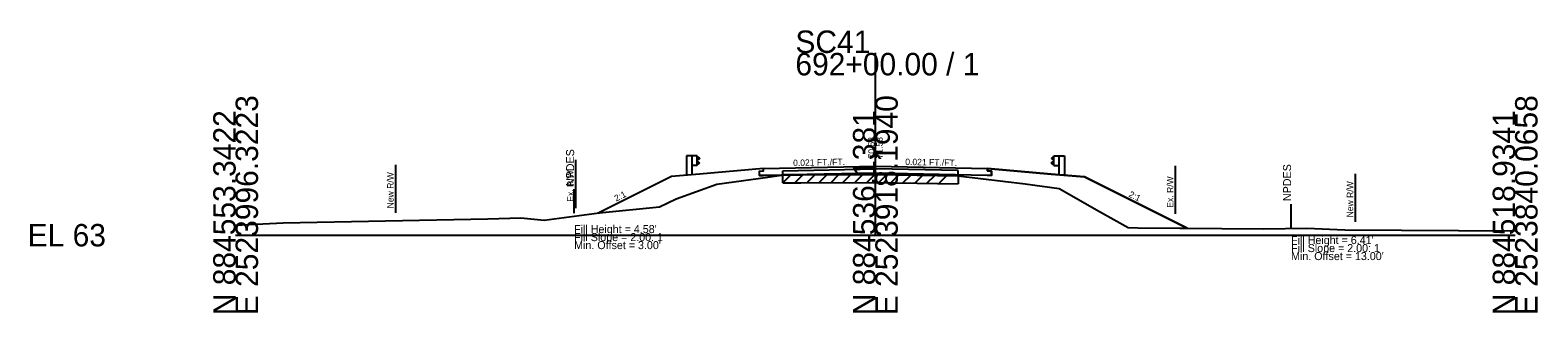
# Model space of a CAD drawing. Extents: x -26 to 183, y -10 to 24021.
# Drawn here: x -25.7 to 162.8, y 17990.3 to 18025.6 of the extents above; entities that cross this region are included whole.
import ezdxf

# ---------------------------------------------------------------- set-up
doc = ezdxf.new("R2010")
doc.units = 0
for name, color, linetype in [('RD_GPK_XS_Cell', 7, 'Continuous'), ('RD_XS_Base', 7, 'Continuous'), ('RD_XS_Buildup', 7, 'Continuous'), ('RD_XS_EarthShd', 7, 'Continuous'), ('RD_XS_EwShp', 7, 'Continuous'), ('RD_XS_ExGround', 7, 'Continuous'), ('RD_XS_ExPaveRet', 7, 'Continuous'), ('RD_XS_ExRW', 7, 'Continuous'), ('RD_XS_GR', 7, 'Continuous'), ('RD_XS_NewRW', 7, 'Continuous'), ('RD_XS_NPDES', 7, 'Continuous'), ('RD_XS_Pave', 7, 'Continuous'), ('RD_XS_TieSlope', 7, 'Continuous'), ('RD_XS_TX_Elev_EX', 7, 'Continuous'), ('RD_XS_TX_Elev_PR', 7, 'Continuous'), ('RD_XS_TX_Slope', 7, 'Continuous'), ('RD_XS_TX_Warning', 7, 'Continuous')]:
    doc.layers.add(name, color=color, linetype=linetype)

msp = doc.modelspace()

# ---------------------------------------------------------------- linework, layer by layer
at = {"layer": 'RD_GPK_XS_Cell'}
for p, q in [((80, 18000), (80, 18022.76)), ((0, 18000), (80, 18000)), ((80, 18000), (160, 18000))]:
    msp.add_line(p, q, dxfattribs=at)
at = {"layer": 'RD_XS_Base'}
for p in [(66.01, 18007.47), (93.99, 18007.47)]:
    msp.add_line(p, (80, 18007.76), dxfattribs=at)
at = {"layer": 'RD_XS_Buildup'}
for p, q in [((68.44, 18008.04), (80, 18008.28)), ((68.44, 18007.54), (68.44, 18008.04)), ((90.35, 18008.06), (80, 18008.28)), ((90.35, 18007.42), (90.35, 18008.06))]:
    msp.add_line(p, q, dxfattribs=at)
at = {"layer": 'RD_XS_EarthShd'}
for p, q in [((58, 18007.64), (54.5, 18007.35)), ((66, 18008.31), (58, 18007.64)), ((94, 18008.31), (102, 18007.64)), ((102, 18007.64), (106.17, 18007.29))]:
    msp.add_line(p, q, dxfattribs=at)
at = {"layer": 'RD_XS_EwShp'}
for points in [[(45.48, 18002.78), (52.99, 18003.54), (55.1, 18004.52), (60.19, 18006.36), (66.56, 18007.26), (68.26, 18007.51), (66.01, 18007.47), (65.5, 18007.46), (65.5, 18008.01), (66, 18008.02), (66, 18008.31), (58, 18007.64), (54.5, 18007.35), (45.33, 18002.76)], [(65.5, 18007.46), (65.5, 18008.01), (66, 18008.02), (66, 18008.31), (58, 18007.64), (54.5, 18007.35), (45.33, 18002.76), (45.48, 18002.78), (52.99, 18003.54), (55.1, 18004.52), (60.19, 18006.36), (66.56, 18007.26), (68.26, 18007.51), (66.01, 18007.47)], [(65.5, 18007.46), (65.5, 18008.01), (66, 18008.02), (66, 18008.31), (58, 18007.64), (54.5, 18007.35), (45.33, 18002.76), (45.48, 18002.78), (52.99, 18003.54), (55.1, 18004.52), (60.19, 18006.36), (66.56, 18007.26), (68.26, 18007.51), (66.01, 18007.47)], [(65.5, 18007.46), (65.5, 18008.01), (66, 18008.02), (66, 18008.31), (58, 18007.64), (54.5, 18007.35), (45.33, 18002.76), (45.48, 18002.78), (52.99, 18003.54), (55.1, 18004.52), (60.19, 18006.36), (66.56, 18007.26), (68.26, 18007.51), (66.01, 18007.47)], [(68.26, 18007.51), (69.36, 18007.54), (68.44, 18007.54)], [(68.44, 18007.54), (69.36, 18007.54), (68.26, 18007.51)], [(68.44, 18007.54), (69.36, 18007.54), (68.26, 18007.51)], [(68.44, 18007.54), (69.36, 18007.54), (68.26, 18007.51)], [(93.99, 18007.47), (80, 18007.76), (69.36, 18007.54), (70.66, 18007.53), (79.56, 18007.59), (80, 18007.58), (82.65, 18007.54), (90.35, 18007.42), (98.71, 18006.4), (103, 18005.83), (108.01, 18002.96), (111.62, 18000.94), (112.84, 18000.93), (118.98, 18000.89), (106.17, 18007.29), (102, 18007.64), (94, 18008.31), (94, 18008.02), (94.5, 18008.01), (94.5, 18007.46)], [(111.62, 18000.94), (112.84, 18000.93), (118.98, 18000.89), (106.17, 18007.29), (102, 18007.64), (94, 18008.31), (94, 18008.02), (94.5, 18008.01), (94.5, 18007.46), (93.99, 18007.47), (80, 18007.76), (69.36, 18007.54), (70.66, 18007.53), (79.56, 18007.59), (80, 18007.58), (82.65, 18007.54), (90.35, 18007.42), (98.71, 18006.4), (103, 18005.83), (108.01, 18002.96)], [(111.62, 18000.94), (112.84, 18000.93), (118.98, 18000.89), (106.17, 18007.29), (102, 18007.64), (94, 18008.31), (94, 18008.02), (94.5, 18008.01), (94.5, 18007.46), (93.99, 18007.47), (80, 18007.76), (69.36, 18007.54), (70.66, 18007.53), (79.56, 18007.59), (80, 18007.58), (82.65, 18007.54), (90.35, 18007.42), (98.71, 18006.4), (103, 18005.83), (108.01, 18002.96)], [(111.62, 18000.94), (112.84, 18000.93), (118.98, 18000.89), (106.17, 18007.29), (102, 18007.64), (94, 18008.31), (94, 18008.02), (94.5, 18008.01), (94.5, 18007.46), (93.99, 18007.47), (80, 18007.76), (69.36, 18007.54), (70.66, 18007.53), (79.56, 18007.59), (80, 18007.58), (82.65, 18007.54), (90.35, 18007.42), (98.71, 18006.4), (103, 18005.83), (108.01, 18002.96)]]:
    msp.add_lwpolyline(points, close=True, dxfattribs=at)
at = {"layer": 'RD_XS_ExGround'}
for p, q in [((60.19, 18006.36), (66.56, 18007.26)), ((66.56, 18007.26), (68.44, 18007.54)), ((68.44, 18007.54), (70.66, 18007.53)), ((70.66, 18007.53), (79.56, 18007.59)), ((79.56, 18007.59), (80, 18007.58)), ((80, 18007.58), (82.65, 18007.54)), ((82.65, 18007.54), (90.35, 18007.42)), ((90.35, 18007.42), (98.71, 18006.4)), ((55.1, 18004.52), (60.19, 18006.36)), ((98.71, 18006.4), (103, 18005.83)), ((103, 18005.83), (108.01, 18002.96)), ((45.48, 18002.78), (52.99, 18003.54)), ((52.99, 18003.54), (55.1, 18004.52)), ((0, 18001.27), (5.93, 18001.53)), ((5.93, 18001.53), (31.53, 18002.03)), ((31.53, 18002.03), (35.66, 18002.16)), ((35.66, 18002.16), (38.59, 18001.88)), ((38.59, 18001.88), (45.48, 18002.78)), ((108.01, 18002.96), (111.62, 18000.94)), ((111.62, 18000.94), (112.84, 18000.93)), ((112.84, 18000.93), (128.58, 18000.81)), ((128.58, 18000.81), (133.96, 18000.86)), ((133.96, 18000.86), (138.7, 18000.68)), ((138.7, 18000.68), (160, 18000.53))]:
    msp.add_line(p, q, dxfattribs=at)
at = {"layer": 'RD_XS_ExPaveRet'}
for p, q in [((68.44, 18006.54), (69.43, 18007.54)), ((68.44, 18006.54), (68.44, 18007.54)), ((69.94, 18006.53), (70.94, 18007.53)), ((71.44, 18006.54), (72.44, 18007.54)), ((72.94, 18006.54), (73.94, 18007.55)), ((74.44, 18006.55), (75.44, 18007.56)), ((75.94, 18006.56), (76.94, 18007.57)), ((77.44, 18006.57), (78.44, 18007.58)), ((78.94, 18006.58), (79.94, 18007.58)), ((80.44, 18006.57), (81.42, 18007.56)), ((81.94, 18006.55), (82.92, 18007.54)), ((83.44, 18006.53), (84.42, 18007.51)), ((84.94, 18006.51), (85.92, 18007.49)), ((86.44, 18006.48), (87.42, 18007.47)), ((87.94, 18006.46), (88.92, 18007.44)), ((90.35, 18007.42), (90.35, 18006.42)), ((68.44, 18006.54), (70.66, 18006.53)), ((70.66, 18006.53), (79.56, 18006.59)), ((79.56, 18006.59), (80, 18006.58)), ((80, 18006.58), (82.65, 18006.54)), ((82.65, 18006.54), (90.35, 18006.42))]:
    msp.add_line(p, q, dxfattribs=at)
at = {"layer": 'RD_XS_ExRW'}
for p, q in [((42.5, 18009.39), (42.5, 18003.39)), ((117.5, 18008.65), (117.5, 18002.65))]:
    msp.add_line(p, q, dxfattribs=at)
at = {"layer": 'RD_XS_GR'}
for p, q in [((56.4, 18009.89), (56.4, 18007.51)), ((57.06, 18009.89), (56.4, 18009.89)), ((57.06, 18009.89), (57.06, 18007.56)), ((57.73, 18009.89), (57.06, 18009.89)), ((57.73, 18008.72), (57.06, 18008.72)), ((57.73, 18008.72), (57.73, 18009.89)), ((57.73, 18009.82), (58, 18009.62)), ((58, 18009.57), (57.73, 18009.37)), ((58, 18009.05), (57.73, 18009.25)), ((57.73, 18008.8), (58, 18009)), ((58, 18009.62), (58, 18009.57)), ((58, 18009), (58, 18009.05)), ((102.3, 18009.81), (102.02, 18009.61)), ((102.02, 18009.61), (102.02, 18009.56)), ((102.02, 18009.56), (102.3, 18009.36)), ((102.02, 18009.04), (102.3, 18009.24)), ((102.02, 18008.99), (102.02, 18009.04)), ((102.3, 18008.79), (102.02, 18008.99)), ((102.3, 18009.89), (102.96, 18009.89)), ((102.3, 18008.72), (102.3, 18009.89)), ((102.3, 18008.72), (102.96, 18008.72)), ((102.96, 18009.89), (102.96, 18007.56)), ((102.96, 18009.89), (103.63, 18009.89)), ((103.63, 18009.89), (103.63, 18007.5)), ((102.96, 18007.56), (102.96, 18007.56))]:
    msp.add_line(p, q, dxfattribs=at)
at = {"layer": 'RD_XS_NewRW'}
for p, q in [((20, 18008.8), (20, 18002.8)), ((140, 18007.67), (140, 18001.67))]:
    msp.add_line(p, q, dxfattribs=at)
at = {"layer": 'RD_XS_NPDES'}
for p, q in [((42.33, 18002.76), (42.33, 18005.76)), ((131.98, 18000.89), (131.98, 18003.89))]:
    msp.add_line(p, q, dxfattribs=at)
at = {"layer": 'RD_XS_Pave'}
for p, q in [((65.5, 18008.01), (66, 18008.02)), ((65.5, 18007.46), (65.5, 18008.01)), ((65.5, 18007.46), (66.01, 18007.47)), ((66, 18008.31), (80, 18008.6)), ((66, 18008.02), (66, 18008.31)), ((80, 18008.6), (94, 18008.31)), ((94.5, 18007.46), (93.99, 18007.47)), ((94, 18008.02), (94, 18008.31)), ((94.5, 18008.01), (94, 18008.02)), ((94.5, 18007.46), (94.5, 18008.01))]:
    msp.add_line(p, q, dxfattribs=at)
at = {"layer": 'RD_XS_TieSlope'}
for p, q in [((54.5, 18007.35), (45.33, 18002.76)), ((106.17, 18007.29), (118.98, 18000.89))]:
    msp.add_line(p, q, dxfattribs=at)

# ---------------------------------------------------------------- texts
at = {"layer": 'RD_GPK_XS_Cell'}
for s, p in [('SC41', (70, 18022.76)), ('692+00.00 / 1', (70, 18019.96)), ('EL 63', (-26, 17998.6))]:
    msp.add_text(s, height=2.8, dxfattribs=at).set_placement(p)
for s, p in [('E 2523996.3223', (2.8, 17990)), ('E 2523918.1940', (82.8, 17990)), ('E 2523840.0658', (162.8, 17990)), ('N 884553.3422', (0, 17990)), ('N 884536.1381', (80, 17990)), ('N 884518.9341', (160, 17990))]:
    msp.add_text(s, height=2.8, rotation=90, dxfattribs=at).set_placement(p)
at = {"layer": 'RD_XS_ExRW'}
for p in [(42.25, 18004.18), (117.25, 18003.43)]:
    msp.add_text('Ex. R/W ', height=0.8, rotation=90, dxfattribs=at).set_placement(p)
at = {"layer": 'RD_XS_NewRW'}
for p in [(19.75, 18003.35), (139.75, 18002.22)]:
    msp.add_text('New R/W ', height=0.8, rotation=90, dxfattribs=at).set_placement(p)
at = {"layer": 'RD_XS_TX_Elev_EX'}
msp.add_text('70.58', height=0.8, rotation=90, dxfattribs=at).set_placement((79.9, 18009.58))
at = {"layer": 'RD_XS_TX_Elev_PR'}
msp.add_text('71.58', height=0.8, rotation=90, dxfattribs=at).set_placement((80.9, 18009.58))
at = {"layer": 'RD_XS_TX_Slope'}
for s, rotation, p in [('0.021 FT./FT.', 1.1916, (69.72, 18008.63)), ('0.021 FT./FT.', 358.8084, (83.73, 18008.77)), ('2:1', 26.5651, (47.6, 18004.18)), ('2:1', 333.4349, (111.6, 18004.84))]:
    msp.add_text(s, height=0.8, rotation=rotation, dxfattribs=at).set_placement(p)
at = {"layer": 'RD_XS_TX_Warning'}
for p in [(42.33, 18005.76), (131.98, 18003.89)]:
    msp.add_text(' NPDES', height=1, rotation=90, dxfattribs=at).set_placement(p)
for s, p in [("Fill Height = 4.58' ", (42.33, 18000.26)), ('Fill Slope = 2.00: 1', (42.33, 17999.26)), ("Min. Offset = 3.00' ", (42.33, 17998.26)), ("Fill Height = 6.41' ", (131.98, 17998.89)), ('Fill Slope = 2.00: 1', (131.98, 17997.89)), ("Min. Offset = 13.00' ", (131.98, 17996.89))]:
    msp.add_text(s, height=1, dxfattribs=at).set_placement(p)

doc.saveas('drawing.dxf')
